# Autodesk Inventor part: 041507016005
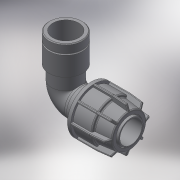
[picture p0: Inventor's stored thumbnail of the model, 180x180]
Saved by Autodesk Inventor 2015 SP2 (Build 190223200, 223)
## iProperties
Created: 2017-08
Part Number: 041507016005
Material: Generic
Description: PLASSON IRRIFIT ELBOW 16-1/2"F
Document SubType Name: Modeling
Designer: KIM
Density: 1 g/cm^3
Appearance: Default
Author: KIM
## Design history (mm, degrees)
derived "041507.ipt"
feature "Solid1::041507.ipt"
tag "TaggingFeature1"
body "Solid1"
other parameters: "d5" = 28.8, "d6" = 12.8, "d10" = 34, "d22" = 22.4, "d24" = 2.4, "d25" = 30.6, "d26" = 27.2, "d31" = 0.8, "d49" = 1.7, "d50" = 0, "d58" = 0.48, "d61" = 360 deg, "d77" = 16, "d78" = 6 deg, "d80" = 17.6, "d81" = 47, "d82" = 2.4, "d84" = 5 deg, "d85" = 70 deg, "d86" = 32.3, "d87" = 0.48, "d88" = 0, "d100" = 27.2, "d101" = 8, "d102" = 0, "d103" = 24.2203, "d107" = 16, "d108" = 20.4941, "d109" = 16, "d110" = 18.631, "d113" = 0.55893, "d120" = 9.4, "d121" = 9.4, "d123" = 20.4941, "d124" = 2.35, "d125" = 90 deg, "d126" = 24.2203, "d127" = 0.55893, "d128" = 6.4, "d129" = 100 deg, "d130" = 20.8, "d_" = 16, "E_" = 34, "A_" = 47, "l_" = 16, "l_2" = 16, "G_" = 18.631, "d99" = 22.4
